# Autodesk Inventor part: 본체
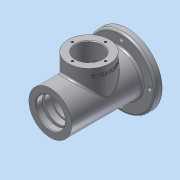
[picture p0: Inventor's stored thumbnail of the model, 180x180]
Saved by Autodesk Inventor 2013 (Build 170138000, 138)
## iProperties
Created: 2016-08
Part Number: 본체
Material: 알루미늄 6061
Document SubType Name: Modeling
Designer: dgall
Density: 1 g/cm^3
Author: dgall
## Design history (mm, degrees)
sketch "스케치1"
  geometry: C1 r 50 at (0, 0); 1 further point
  constraints: 1 centre point, 1 coincident
  dimensions: "d0" = 100 diameter of C1
extrude "돌출1" new body sketch "스케치1" distance "d2" = 10; taper "d3" = 0 deg
sketch "스케치2"
  geometry: C1 r 50 at (0, 0) reference; C2 r 31 at (0, 0)
  constraints: 1 centre point, 1 coincident
  dimensions: "d4" = 62 diameter of C2
extrude "돌출2" join sketch "스케치2" distance "d6" = 3; taper "d7" = 0 deg
sketch "스케치3"
  geometry: C1 r 50 at (0, 0) reference; C2 r 31 at (0, 0)
  constraints: 1 centre point, 1 coincident
  dimensions: "d8" = 62 diameter of C2
extrude "돌출3" join sketch "스케치3" distance "d10" = 102; taper "d11" = 0 deg
fillet "모깎기1" dims "d12" = 3
fillet "모깎기2" dims "d13" = 3
sketch "스케치4" dims "d14" = 83
  geometry: C1 r 31 at (0, 0) reference; C2 r 50 at (0, 0) reference; C3 r 4 at (0, 41.5); 1 further point
  constraints: 2 vertical alignment, 1 centre point, 1 coincident, 2 other
  dimensions: "d16" = 8 diameter of C3
hole "구멍1" sketch "스케치4" at (0, 41.5) diameter "d17" = 6.647; stored, may be unused: countersink angle "d21" = 90 deg, drill point angle "d23" = 118 deg; dims "d18" = 6, "d19" = 4, "d20" = 2, "d22" = 8
node "작업 평면1"
sketch "스케치5"
  geometry: L1 (-31, -102)-(31, -102) reference; C1 r 30 at (0, -46); 1 further point
  constraints: 1 centre point
  dimensions: "d28" = 0 horizontal distance of point (0, 0) C1.centre; "d29" = 56 distance from line of C1.centre L1; "d30" = 60 diameter of C1
extrude "돌출4" join sketch "스케치5" stored distance "d31" = 102; taper "d32" = 0 deg
fillet "모깎기3" dims "d33" = 3
sketch "스케치6"
  geometry: C1 r 31 at (0, 0) reference; C2 r 21 at (0, 0)
  constraints: 1 centre point, 1 coincident
  dimensions: "d34" = 42 diameter of C2
extrude "돌출5" cut sketch "스케치6" distance "d36" = 14; taper "d37" = 0 deg
sketch "스케치7"
  geometry: C1 r 31 at (0, 0) reference; C2 r 21 at (0, 0)
  constraints: 1 centre point, 1 coincident
  dimensions: "d38" = 42 diameter of C2
extrude "돌출6" cut sketch "스케치7" distance "d40" = 9; taper "d41" = 0 deg
chamfer "모따기1" distance "d42" = 1; stored, may be unused: second distance "d43" = 2, angle "d44" = 45 deg
sketch "스케치8"
  geometry: C1 r 21 at (0, 0) reference; C2 r 12.5 at (0, 0)
  constraints: 1 centre point, 1 coincident
  dimensions: "d45" = 25 diameter of C2
extrude "돌출7" cut sketch "스케치8" distance "d47" = 0.7; taper "d48" = -30 deg
fillet "모깎기4" dims "d49" = 3
sketch "스케치9"
  geometry: C1 r 12.096 at (0, 0) reference; C2 r 12.5 at (0, 0)
  constraints: 1 centre point, 1 coincident
  dimensions: "d50" = 25 diameter of C2
extrude "돌출8" cut sketch "스케치9" distance "d52" = 6.6; taper "d53" = 0 deg
sketch "스케치10"
  geometry: C1 r 12.096 at (0, 0) reference; C2 r 10 at (0, 0)
  constraints: 1 centre point, 1 coincident
  dimensions: "d54" = 20 diameter of C2
extrude "돌출9" cut sketch "스케치10" distance "d56" = 2.7; taper "d57" = 0 deg
fillet "모깎기5" dims "d58" = 0.3
sketch "스케치11"
  geometry: C1 r 10 at (0, 0) reference; C2 r 16.5 at (0, 0)
  constraints: 1 centre point, 1 coincident
  dimensions: "d59" = 33 diameter of C2
extrude "돌출10" cut sketch "스케치11" distance "d61" = 10; taper "d62" = 0 deg
sketch "스케치12"
  geometry: C1 r 10 at (0, 0) reference
extrude "돌출11" cut sketch "스케치12" distance "d63" = 10; taper "d64" = 0 deg
sketch "스케치13"
  geometry: C1 r 30 at (0, 0) reference; C2 r 2 at (-24, 0); C3 r 2 at (0, -24); C4 r 2 at (24, 0); C5 r 2 at (0, 24); A1 r 24 centre (0, 0) between (-24, 0) and (0, -24); 1 further point
  constraints: 5 centre point, 4 point on circle, 2 horizontal alignment, 2 vertical alignment, 1 coincident
  dimensions: "d65" = 48 diameter of A1; "d67" = 4 diameter of C2; "d68" = 4 diameter of C3; "d69" = 4 diameter of C4; "d70" = 4 diameter of C5
hole "구멍2" sketch "스케치13" at (0, -24), (24, 0), (-24, 0), (0, 24) diameter "d71" = 3.242; stored, may be unused: countersink angle "d75" = 90 deg, drill point angle "d77" = 118 deg; dims "d72" = 8, "d73" = 4, "d74" = 2, "d76" = 10
sketch "스케치14"
  geometry: C1 r 21 at (0, 0) reference; C2 r 24 at (0, 0)
  constraints: 1 centre point, 1 coincident
  dimensions: "d78" = 48 diameter of C2
extrude "돌출12" cut sketch "스케치14" distance "d80" = 3; taper "d81" = 0 deg
sketch "스케치15"
  geometry: C1 r 21 at (0, 0) reference
extrude "돌출13" cut sketch "스케치15" distance "d82" = 3; taper "d83" = 0 deg
sketch "스케치16"
  geometry: C1 r 24 at (0, 0) reference; C2 r 20 at (0, 0)
  constraints: 1 centre point, 1 coincident
  dimensions: "d84" = 40 diameter of C2
extrude "돌출14" cut sketch "스케치16" distance "d86" = 9; taper "d87" = 0 deg
sketch "스케치17"
  geometry: C1 r 20 at (0, 0) reference; C2 r 17.5 at (0, 0)
  constraints: 1 centre point, 1 coincident
  dimensions: "d88" = 35 diameter of C2
extrude "돌출15" cut sketch "스케치17" distance "d90" = 24.25; taper "d91" = 0 deg
sketch "스케치18"
  geometry: C1 r 17.5 at (0, 0) reference; C2 r 18.5 at (0, 0)
  constraints: 1 centre point, 1 coincident
  dimensions: "d92" = 37 diameter of C2
extrude "돌출16" cut sketch "스케치18" distance "d94" = 1.75; taper "d95" = 0 deg
sketch "스케치20"
  geometry: C1 r 17.5 at (0, 0) reference; C2 r 17.5 at (0, 0)
  constraints: 1 centre point, 1 coincident
  dimensions: "d96" = 35 diameter of C2
extrude "돌출17" cut sketch "스케치20" distance "d98" = 1.75; taper "d99" = 0 deg
sketch "스케치21"
  geometry: C1 r 18.5 at (0, 0) reference; C2 r 26 at (0, 0)
  constraints: 1 centre point, 1 coincident
  dimensions: "d100" = 52 diameter of C2
extrude "돌출18" cut sketch "스케치21" distance "d101" = 38; taper "d102" = 0 deg
sketch "스케치22"
  geometry: C1 r 18.5 at (0, 0) reference
extrude "돌출19" cut sketch "스케치22" distance "d103" = 38; taper "d104" = 0 deg
sketch "스케치23"
  geometry: C1 r 30 at (0, 0) reference; C2 r 19 at (0, 0); 1 further point
  constraints: 1 centre point, 1 coincident
  dimensions: "d105" = 38 diameter of C2
extrude "돌출20" cut sketch "스케치23" stored distance "d107" = 38; taper "d108" = 0 deg
chamfer "모따기2" distance "d109" = 1; stored, may be unused: second distance "d110" = 2, angle "d111" = 45 deg
node "작업 평면2"
sketch "스케치25"
  geometry: L1 (-66.739, 42.002)-(-25.261, 42.002); L2 (-25.261, 42.002)-(-25.261, 35.998); L3 (-25.261, 35.998)-(-66.739, 35.998); L4 (-66.739, 35.998)-(-66.739, 42.002); L5 (-66.739, 39)-(-25.261, 39); L6 (-46, 42.002)-(-46, 35.998); L7 (-76, 49)-(-16, 49) reference; L8 (-102, 31)-(-102, -31) reference; 1 further point
  constraints: 4 end point, 4 midpoint, 2 other
  dimensions: "d113" = 10 distance from line of L5.end L7; "d114" = 56 distance between parallel lines of L6 L8
feature "엠보싱1" sketch "스케치25" dims "d0" = 100, "d115" = 0.5, "d116" = 0
fillet "모깎기6" dims "d117" = 3
node "솔리드1"
pattern_circular "원형 패턴1" dims angle "d25" = 360 deg
other parameters: "d27" = 49, "d112" = 51.5
